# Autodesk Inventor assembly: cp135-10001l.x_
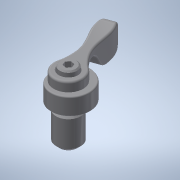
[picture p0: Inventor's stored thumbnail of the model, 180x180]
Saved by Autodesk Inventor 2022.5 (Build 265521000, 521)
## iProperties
Part Number: cp135-10001l.x_
Material: 一般
Document SubType Name: Assembly
Designer: ImaoCorp
Sending System: SOLIDWORKS 2017-2017317
MC: AMD64
MC_MODEL: Intel64 Family 6 Model 60 Stepping 3, GenuineIntel
OS: Windows_NT
FRU: Parasolid Version 29.0, build 201,  4-17-2017
FORMAT: text
GUISE: transmit
KEY: cp135-10001l
FILE: cp135-10001l.x_t
DATE: Thu Apr 04 16:37:46 2019
Author: ImaoCorp
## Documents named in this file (3)
- X:\14_SW2022-Inv2022\00_全2023-1023新製品(TCC)まで\c\cp135-10001l\CP135-10001L.iam
- X:\14_SW2022-Inv2022\00_全2023-1023新製品(TCC)まで\c\cp135-10001l\cp135-10001l_01.ipt
- X:\14_SW2022-Inv2022\00_全2023-1023新製品(TCC)まで\c\cp135-10001l\cp135-10001l_02.ipt
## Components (2 placed, 2 different names)
1. cp135-10001l_01
2. cp135-10001l_02
